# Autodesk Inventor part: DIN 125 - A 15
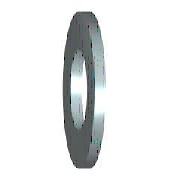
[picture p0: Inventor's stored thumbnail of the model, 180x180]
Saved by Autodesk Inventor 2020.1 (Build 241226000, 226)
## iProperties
Manager: www.cadconsulting.pl
Company: Fabian Stasiak CAD Consulting
Created: 2006-02
Part Number: DIN 125 - A 15
Material: Stal, miękka
Description: Podkładka
Document SubType Name: Modeling
Standard: DIN 125
Designer: F.Stasiak
Standards Organization: DIN
Language: pl-PL
Size Designation: A 15
Categories: <MemberInstance><Categories><Category DisplayName="Mocowania" InternalName="e4da775c-781d-43d5-af7c-5136215cf5a6" Mnemonic="FSTN"><Category DisplayName="Podkład
Density: 7.85 g/cm^3
Appearance: Stal
Mass: 8.61611 g
Surface Area: 12.158 cm^2
Volume: 1.09759 cm^3
Author: F.Stasiak
Subject: Zbiór ćwiczeń. Autodesk Inventor 2020. Kurs podstawowy
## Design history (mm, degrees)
sketch "Szkic"
  geometry: C1 r 14 at (0, 0); C2 r 7.5 at (0, 0); 1 further point
  constraints: 2 centre point, 2 coincident
  dimensions: "d0" = 15 diameter of C2 (= SD1); "d1" = 28 diameter of C1 (= SD2)
extrude "Bryła" new body sketch "Szkic" distance "d2" = 2.5 (= SD); taper "d3" = 0 deg
workaxis "Work Axis1"
workplane "Work Plane1"
node "Bryła1"
node "Korpusy bryłowe"
node "Korpusy powierzchniowe"
other parameters: "SD1" = 15 [user parameter; used in 1 equation term], "SD2" = 28 [user parameter; used in 1 equation term], "SD" = 2.5 [user parameter; used in 1 equation term], "d4" = 0, "d5" = 0, "d6" = 0, "d7" = 0, "NND" = 14 [user parameter]
